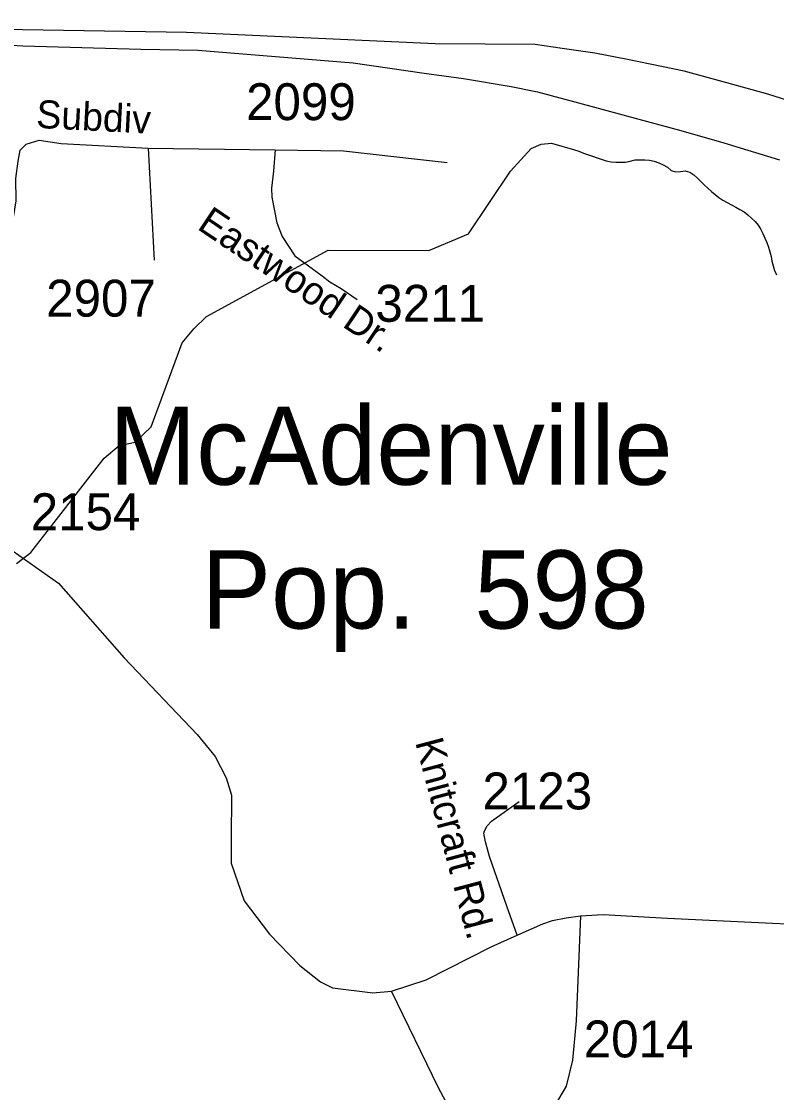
# Model space of a CAD drawing. Extents: x 1364363 to 1407445, y 538563 to 573342.
# Drawn here: x 1383308 to 1385868, y 553914 to 557543 of the extents above; entities that cross this region are included whole.
import ezdxf

# ---------------------------------------------------------------- set-up
doc = ezdxf.new("R2010")
doc.units = 0
for name, color, linetype in [('Exist Civil Demographics City Label', 7, 'Continuous'), ('Exist Hydrographic Creek Single Shore', 7, 'Continuous'), ('Exist Road Primary Interstate Divided Center Attributed', 7, 'Continuous'), ('Exist Road Primary NC Attributed', 7, 'Continuous'), ('Exist Road Secondary Type 51 Attributed', 7, 'Continuous'), ('Exist Road Secondary Type 51 Label', 7, 'Continuous'), ('Exist Road Secondary Type 51 Number Label', 7, 'Continuous')]:
    doc.layers.add(name, color=color, linetype=linetype)

msp = doc.modelspace()

# ---------------------------------------------------------------- linework, layer by layer
at = {"layer": 'Exist Hydrographic Creek Single Shore'}
for points in [[(1383291.2, 555706.9), (1383339.7, 555744), (1383587.8, 556063.6), (1383639.2, 556106.4), (1383693.3, 556117.9), (1383747.5, 556169.2), (1383853.1, 556454.6), (1383891.8, 556501.1), (1383935.8, 556543.1), (1384347.8, 556767.6), (1384688.8, 556767.3), (1384823.8, 556823.6), (1384966.2, 557035.3), (1385036.7, 557112.7), (1385069.9, 557127.7), (1385104.9, 557130.9)], [(1385104.9, 557130.9), (1385182.7, 557108.3), (1385198.3, 557103.3), (1385213.6, 557097.1), (1385291, 557071), (1385306.9, 557067.5), (1385323.2, 557066), (1385339.8, 557066), (1385356.2, 557066.7), (1385372.3, 557069.9), (1385388.3, 557073.8), (1385404.6, 557074.6), (1385421.1, 557074.3), (1385437.5, 557072.8), (1385453.6, 557069.6), (1385469.2, 557064.2), (1385483.9, 557057.3), (1385498.2, 557049.1), (1385511.1, 557038.4), (1385525.9, 557033.2), (1385542.5, 557034.4), (1385558, 557037), (1385574, 557032.8), (1385587.7, 557023.7), (1385599.7, 557012.6), (1385611.4, 557001), (1385622.9, 556989.4), (1385634.9, 556978.2), (1385647.3, 556967.4), (1385660.1, 556956.9), (1385673.1, 556946.9), (1385686.6, 556937.8), (1385700.8, 556929.5), (1385715.2, 556921.7), (1385729.8, 556914), (1385744.1, 556906.1), (1385758.2, 556897.5), (1385771.1, 556887.4), (1385783.2, 556876.2), (1385795.2, 556864.8), (1385806, 556852.5), (1385814.6, 556838.7), (1385821.9, 556824.1), (1385828.7, 556808.9), (1385835.2, 556793.8), (1385841, 556778.5), (1385845.9, 556762.8), (1385849.6, 556746.8), (1385852.8, 556730.7), (1385856.3, 556714.6), (1385861, 556699), (1385868.4, 556684.2)]]:
    msp.add_lwpolyline(points, dxfattribs=at)
at = {"layer": 'Exist Road Primary Interstate Divided Center Attributed'}
for points in [[(1385949.5, 557261.4), (1385838.7, 557297.2), (1385700.2, 557335.7), (1385555.5, 557374.9), (1385363.2, 557413.7), (1385252.4, 557436.1), (1385141.6, 557451), (1385049.2, 557464.5), (1384710.8, 557467.7), (1384340.5, 557484.4), (1383867.5, 557505.6), (1383242.8, 557515.9), (1383100.7, 557529.7), (1382890.4, 557540.7), (1382578.3, 557543.3)], [(1382531.5, 557481.6), (1382859.6, 557470.5), (1383105.1, 557472.7), (1383312.1, 557460.7), (1383713, 557449.7), (1383905.8, 557445.3), (1384433.1, 557402.9), (1384673, 557367.4), (1384806.8, 557349.5), (1384968.4, 557322.6), (1385057.7, 557304.7), (1385197, 557267.4), (1385401.7, 557212.1), (1385543.2, 557173.3), (1385689.4, 557131.5), (1385878, 557074.8)]]:
    msp.add_lwpolyline(points, dxfattribs=at)
at = {"layer": 'Exist Road Primary NC Attributed'}
for points in [[(1382967.3, 555804), (1383013.6, 555822.5), (1383078.4, 555831.8), (1383132.1, 555826.2), (1383213.5, 555792.9), (1383280.2, 555748.4), (1383433.1, 555640.3), (1383656, 555386.5), (1383904, 555127.1), (1383965.1, 555052.7), (1384002.1, 554980.4), (1384020.1, 554921.9), (1384018.8, 554773), (1384018.8, 554691.5), (1384063.2, 554563.7), (1384148.4, 554450.7), (1384251.5, 554344), (1384321.8, 554288.4), (1384362.6, 554268), (1384499.6, 554251.4), (1384562.1, 554257.3)], [(1384989.1, 554447.4), (1385076.1, 554485.7), (1385108.6, 554496.2), (1385155, 554505.2), (1385203.6, 554513)], [(1385203.6, 554513), (1385280.8, 554517.4), (1385498.7, 554505), (1386258.9, 554467.9), (1386592.8, 554454.5)], [(1384562.1, 554257.3), (1384679.9, 554295.8), (1384900.2, 554407.4), (1384989.1, 554447.4)]]:
    msp.add_lwpolyline(points, dxfattribs=at)
at = {"layer": 'Exist Road Secondary Type 51 Attributed'}
for q in [(1383757.4, 556734.6), (1384168.4, 557108.4)]:
    msp.add_line((1383737, 557113.9), q, dxfattribs=at)
for points in [[(1383247.8, 556802.5), (1383281.3, 556879.3), (1383290.4, 556935.1), (1383288.9, 557010.6), (1383296.4, 557069.5), (1383303.9, 557106.9), (1383324.2, 557127.3), (1383367.4, 557140.6), (1383442.7, 557129.1), (1383737, 557113.9)], [(1384168.4, 557108.4), (1384162.8, 557036.1), (1384155.4, 556978.7), (1384157.3, 556947.2), (1384173.9, 556860.5), (1384192.4, 556814.2), (1384235, 556749.4), (1384327.6, 556680.9), (1384353.5, 556660.5), (1384391.4, 556637.9), (1384446.1, 556601.2)], [(1384168.4, 557108.4), (1384400.1, 557104.9), (1384751.5, 557065.7)], [(1384989.1, 554447.4), (1384953.9, 554544.8), (1384894.6, 554713.6), (1384881.5, 554763.1), (1384877.7, 554780.3), (1384876.2, 554792.3), (1384878.3, 554800), (1384886.7, 554816.9), (1384901.2, 554833.6), (1384995.9, 554899.9)], [(1385203.6, 554513), (1385189.2, 554157.2), (1385176.5, 554023.4), (1385154.7, 553935.8), (1385117.4, 553872.6), (1385056, 553813.8), (1384864.9, 553663.7)], [(1384864.9, 553663.7), (1384721.7, 553929.8), (1384562.1, 554257.3)]]:
    msp.add_lwpolyline(points, dxfattribs=at)

# ---------------------------------------------------------------- texts
at = {"layer": 'Exist Civil Demographics City Label'}
for s, p in [('McAdenville', (1383605.4, 555973.3)), ('Pop.  598', (1383917.8, 555486.1))]:
    msp.add_text(s, height=265, dxfattribs=at).set_placement(p)
at = {"layer": 'Exist Road Secondary Type 51 Label'}
for s, rotation, p in [('Subdiv', 357.0459, (1383356.4, 557182.8)), ('Eastwood Dr.', 326.1245, (1383899.8, 556842)), ('Knitcraft Rd.', 284.8962, (1384642.2, 555101.5))]:
    msp.add_text(s, height=95, rotation=rotation, dxfattribs=at).set_placement(p)
at = {"layer": 'Exist Road Secondary Type 51 Number Label'}
for s, p in [('2099', (1384069.5, 557208.7)), ('2907', (1383391.7, 556542.9)), ('3211', (1384507.9, 556525.5)), ('2154', (1383339.3, 555819.3)), ('2123', (1384871, 554873.1)), ('2014', (1385214.5, 554032.8))]:
    msp.add_text(s, height=125, dxfattribs=at).set_placement(p)

doc.saveas('drawing.dxf')
